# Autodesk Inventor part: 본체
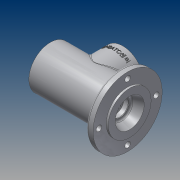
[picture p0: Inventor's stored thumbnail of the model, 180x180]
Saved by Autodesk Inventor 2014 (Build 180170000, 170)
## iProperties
Created: 2016-08
Part Number: 본체
Material: 알루미늄 6061
Document SubType Name: Modeling
Designer: 406-05
Mass: 731.257 g
Surface Area: 615.488 cm^2
Volume: 269.837 cm^3
Density: 2.71 g/cm^3
Appearance: 알루미늄 - 평지
Author: 406-05
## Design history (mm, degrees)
sketch "스케치1"
  geometry: L1 (-57.5, 0)-(-57.5, 31); L2 (-57.5, 31)-(57.5, 31); L3 (57.5, 31)-(57.5, 0); L4 (57.5, 21)-(45.491, 16.711); L5 (43.5, 13.886)-(43.5, 12.904); L6 (42.8, 12.5)-(36.5, 12.5); L7 (36.2, 12.2)-(36.2, 10); L8 (36.2, 10)-(33.5, 10); L9 (33.5, 10)-(33.5, 13); L10 (30.5, 16)-(28.5, 16); L11 (28.5, 16)-(28.5, 17.2); L12 (28.2, 17.5)-(-31.5, 17.5); L13 (-31.5, 17.5)-(-31.5, 18.5); L14 (-31.5, 18.5)-(-33.25, 18.5); L15 (-33.25, 18.5)-(-33.25, 17.5); L16 (-33.25, 17.5)-(-36.5, 17.5); L17 (-36.5, 17.5)-(-36.5, 20); L18 (-36.5, 20)-(-45.5, 20); L19 (-45.5, 20)-(-45.5, 24); L20 (-45.5, 24)-(-48.5, 24); L21 (-48.5, 24)-(-48.5, 0); L22 (42.8, 12.5)-(43.5, 12.904); L23 (-1.5, 49)-(-1.5, 0); L24 (-1.5, 49)-(-31.5, 49); L25 (-31.5, 49)-(-31.5, 0); L26 (54.5, 0)-(54.5, 50); L27 (54.5, 50)-(44.5, 50); L28 (44.5, 50)-(44.5, 0); L29 (-20.5, 0)-(-20.5, -23); L30 (-17.5, -26)-(14.5, -26); L31 (17.5, -23)-(17.5, 0); L32 (-48.5, 0)-(57.5, 0); L33 (57.5, 0)-(57.5, 21); A1 r 0.3 centre (28.2, 17.2) between (28.5, 17.2) and (28.2, 17.5); A2 r 0.3 centre (36.5, 12.2) between (36.5, 12.5) and (36.2, 12.2); A3 r 3 centre (46.5, 13.886) between (45.491, 16.711) and (43.5, 13.886); A4 r 3 centre (30.5, 13) between (33.5, 13) and (30.5, 16); A5 r 3 centre (-17.5, -23) between (-20.5, -23) and (-17.5, -26); A6 r 3 centre (14.5, -23) between (14.5, -26) and (17.5, -23); 9 further points
  constraints: 66 end point, 13 perpendicular, 13 point on line, 12 point on circle, 12 tangent, 11 parallel, 6 centre point, 5 vertical, 3 equal radius, 2 collinear, 1 coincident, 1 midpoint, 1 vertical alignment, 11 other
  dimensions: "d0" = 115 distance of L1.start L3.end; "d1" = 62 dimension on L2; "d2" = 42 dimension on L4.start; "d3" = 32 dimension on point (43.5, 16); "d4" = 25 dimension on L6; "d5" = 20 dimension on L8; "d6" = 32 dimension on L10; "d7" = 35 dimension on L12; "d8" = 37 dimension on L14; "d9" = 35 dimension on L16; "d10" = 40 dimension on L18; "d11" = 48 dimension on L20; "d12" = 14 distance between parallel lines of L5 L3; "d15" = 24 distance between parallel lines of L3 L9; "d17" = 7.3 distance of point (43.5, 12.5) point (36.2, 12.5); "d18" = 12 distance between parallel lines of L19 L1; "d19" = 3 distance of L19.end L20.end; "d20" = 21 distance between parallel lines of L1 L17; "d21" = 26 distance between parallel lines of L1 L13; "d22" = 1.75 distance of L13.end L14.end; "d23" = 60 distance of point (28.5, 17.5) L12.end; "d24" = 0.3 radius of A1; "d25" = 0.7 distance of L6.start point (43.5, 12.5); "d26" = 30 deg angle of L6 L22; "d27" = 3 radius of A3; "d28" = 56 distance between parallel lines of L23 L1; "d29" = 60 diameter of L25 L23; "d30" = 49 distance from line of L24 point (0, 0); "d31" = 3 distance between parallel lines of L26 L3; "d32" = 10 distance between parallel lines of L28 L26; "d33" = 100 dimension on L27; "d34" = 38 distance between parallel lines of L29 L31; "d35" = 52 dimension on L30; "d86" = 3 radius of A5
revolve "회전1" stored, may be unused: angle "d36" = 90 deg
revolve "회전2" stored, may be unused: angle "d37" = 90 deg
revolve "회전3" stored, may be unused: angle "d38" = 90 deg
hole "구멍1" diameter "d41" = 38; stored, may be unused: countersink angle "d45" = 90 deg, drill point angle "d47" = 118 deg; dims "d39" = 10, "d40" = 10, "d42" = 6, "d43" = 4, "d44" = 2, "d46" = 8
hole "구멍2" diameter "d50" = 40.376; stored, may be unused: countersink angle "d54" = 90 deg, drill point angle "d56" = 118 deg; dims "d48" = 10, "d49" = 10, "d51" = 6, "d52" = 4, "d53" = 2, "d55" = 9
chamfer "모따기1" distance "d57" = 1; stored, may be unused: second distance "d58" = 2, angle "d59" = 45 deg
sketch "스케치2"
  geometry: C1 r 30 at (0, 0) reference; 5 further points
  constraints: 1 vertical alignment, 5 other
  dimensions: "d60" = 24 distance of point (0, 24) C1.centre; "d63" = 360 deg dimension on C1.centre point (0, 24) (derived)
hole "구멍3" sketch "스케치2" at (0, 24), (-24, 0), (0, -24), (24, 0) diameter "d65" = 3.242; stored, may be unused: countersink angle "d69" = 90 deg, drill point angle "d71" = 118 deg; dims "d66" = 8, "d67" = 4, "d68" = 2, "d70" = 10
sketch "스케치3"
  geometry: 5 further points
  constraints: 1 vertical alignment, 5 other
  dimensions: "d72" = 41.5 distance of point (0, 41.5) point (0, 0); "d75" = 360 deg dimension on point (0, 0) point (0, 41.5) (derived)
hole "구멍4" sketch "스케치3" at (0, 41.5), (-41.5, 0), (0, -41.5), (41.5, 0) diameter "d77" = 8; stored, may be unused: countersink angle "d81" = 90 deg, drill point angle "d83" = 118 deg; dims "d78" = 8, "d79" = 4, "d80" = 2, "d82" = 10
fillet "모깎기1" dims "d84" = 3
node "작업 평면1"
sketch "스케치4"
  geometry: L1 (-56, -55.5)-(-56, 6.5) reference; L2 (30, 24.5)-(-30, 24.5) reference; 2 further points
  constraints: 1 other
  dimensions: "d87" = 56 distance from line of L1 point (0, 14.5); "d88" = 10 distance from line of point (0, 14.5) L2
feature "엠보싱1" sketch "스케치4" dims "d1" = 62, "d89" = 0.5, "d90" = 0
node "솔리드1"
